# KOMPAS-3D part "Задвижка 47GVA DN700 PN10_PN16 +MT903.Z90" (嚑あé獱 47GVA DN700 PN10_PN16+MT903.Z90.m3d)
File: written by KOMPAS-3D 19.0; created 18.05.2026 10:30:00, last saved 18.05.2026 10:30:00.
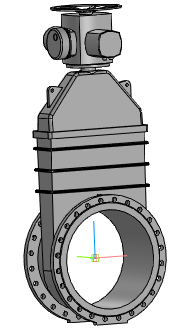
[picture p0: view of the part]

Document properties: Автор: Энергия; Полное имя файла: ..\Задвижка 47GVA DN40_DN1000+MT903.Z\Задвижка 47GVA DN700 PN10_PN16+MT903.Z90.a3d

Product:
- Part/product: Задвижка 47GVA DN700 PN10_PN16 +MT903.Z90
    Масса: 1727.58
  - Body: Электропривод MT903.Z90-120
      Масса: 369.82
  - Body: Задвижка 47GVA DN700 PN10_PN16_F25 без исполнительного механизма
      Масса: 1357.76

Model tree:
1. Операция без истории:1
2. Операция без истории:2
